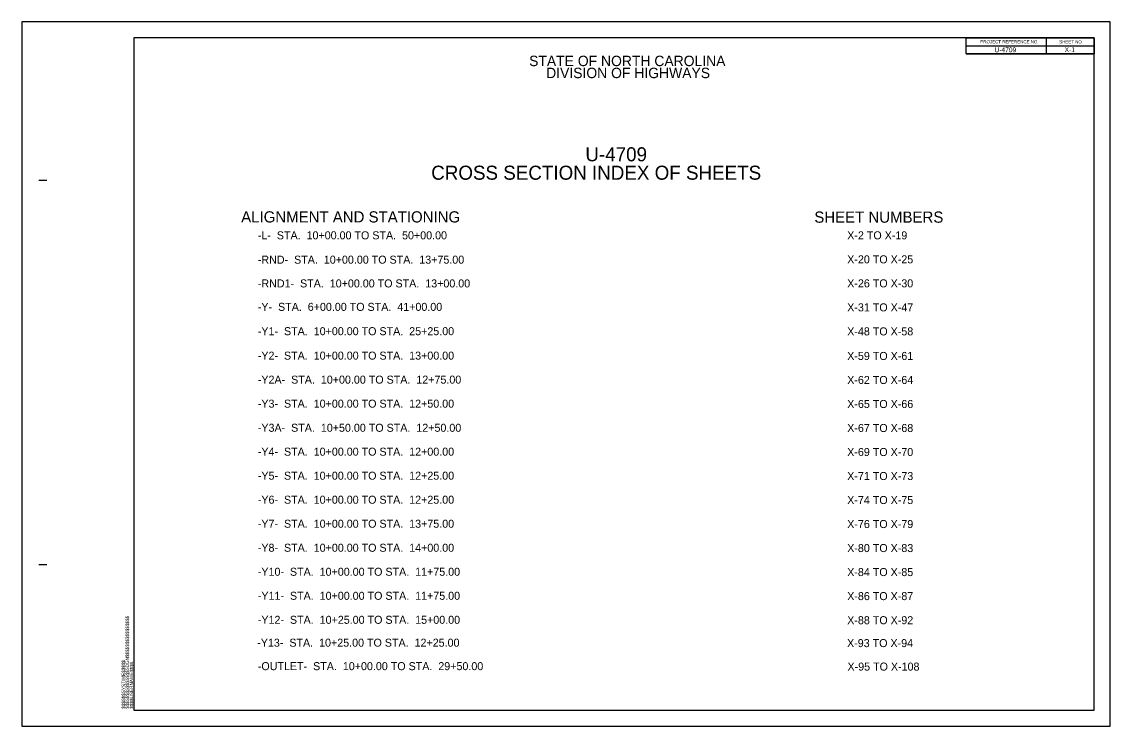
# Model space of a CAD drawing. Extents: x 573852.9 to 573886.9, y -53297.7 to -53275.7.
import ezdxf

# ---------------------------------------------------------------- set-up
doc = ezdxf.new("R2010")
doc.units = 0
for name, color, linetype in [('Sheet Data Field CELL', 7, 'Continuous'), ('Sheet Plot Border Outside CELL', 7, 'Continuous'), ('Sheet Summary CELL', 7, 'Continuous')]:
    doc.layers.add(name, color=color, linetype=linetype)

msp = doc.modelspace()

# ---------------------------------------------------------------- linework, layer by layer
at = {"layer": 'Sheet Plot Border Outside CELL'}
msp.add_lwpolyline([(573852.921, -53297.659), (573886.921, -53297.659), (573886.921, -53275.659), (573852.921, -53275.659)], close=True, dxfattribs=at)
at = {"layer": 'Sheet Summary CELL'}
for p, q in [((573856.421, -53276.159), (573856.421, -53276.968)), ((573884.921, -53276.16), (573884.921, -53276.66)), ((573882.42, -53276.41), (573886.421, -53276.41)), ((573882.42, -53276.66), (573886.421, -53276.66)), ((573853.451, -53280.609), (573853.701, -53280.609)), ((573853.451, -53292.609), (573853.701, -53292.609)), ((573856.421, -53297.159), (573856.421, -53297.159)), ((573856.421, -53297.159), (573856.421, -53297.159)), ((573856.421, -53297.159), (573856.421, -53297.159)), ((573856.421, -53297.159), (573856.421, -53297.159)), ((573856.421, -53297.159), (573856.421, -53297.159)), ((573856.421, -53297.159), (573856.421, -53297.159))]:
    msp.add_line(p, q, dxfattribs=at)
for points in [[(573886.421, -53276.159), (573856.421, -53276.159), (573856.421, -53297.159), (573886.421, -53297.159)], [(573882.42, -53276.159), (573886.421, -53276.159), (573886.421, -53276.66), (573882.42, -53276.66)]]:
    msp.add_lwpolyline(points, close=True, dxfattribs=at)
msp.add_lwpolyline([(573859.171, -53297.159), (573859.171, -53297.159)], dxfattribs=at)

# ---------------------------------------------------------------- texts
at = {"layer": 'Sheet Data Field CELL'}
for s, p in [('U-4709', (573883.305, -53276.61)), ('X-1', (573885.497, -53276.604))]:
    msp.add_text(s, height=0.15, dxfattribs=at).set_placement(p)
at = {"layer": 'Sheet Summary CELL'}
for s, height, p in [('PROJECT REFERENCE NO.', 0.1, (573882.864, -53276.333)), ('SHEET NO.', 0.1, (573885.327, -53276.335)), ('STATE OF NORTH CAROLINA', 0.325, (573868.769, -53277.044)), ('DIVISION OF HIGHWAYS', 0.325, (573869.301, -53277.419)), ('U-4709', 0.439, (573870.526, -53280.017)), ('CROSS SECTION INDEX OF SHEETS', 0.439, (573865.71, -53280.592)), ('ALIGNMENT AND STATIONING', 0.35, (573859.775, -53281.927)), ('SHEET NUMBERS', 0.35, (573877.677, -53281.934)), ('-L-  STA.  10+00.00 TO STA.  50+00.00', 0.25, (573860.294, -53282.453)), ('X-2 TO X-19', 0.25, (573878.705, -53282.453)), ('-RND-  STA.  10+00.00 TO STA.  13+75.00', 0.25, (573860.294, -53283.213)), ('X-20 TO X-25', 0.25, (573878.705, -53283.203)), ('-RND1-  STA.  10+00.00 TO STA.  13+00.00', 0.25, (573860.294, -53283.955)), ('X-26 TO X-30', 0.25, (573878.705, -53283.953)), ('-Y-  STA.  6+00.00 TO STA.  41+00.00', 0.25, (573860.294, -53284.687)), ('X-31 TO X-47', 0.25, (573878.705, -53284.703)), ('-Y1-  STA.  10+00.00 TO STA.  25+25.00', 0.25, (573860.294, -53285.447)), ('X-48 TO X-58', 0.25, (573878.705, -53285.453)), ('-Y2-  STA.  10+00.00 TO STA.  13+00.00', 0.25, (573860.294, -53286.21)), ('X-59 TO X-61', 0.25, (573878.705, -53286.22)), ('-Y2A-  STA.  10+00.00 TO STA.  12+75.00', 0.25, (573860.294, -53286.96)), ('X-62 TO X-64', 0.25, (573878.705, -53286.97)), ('-Y3-  STA.  10+00.00 TO STA.  12+50.00', 0.25, (573860.294, -53287.71)), ('X-65 TO X-66', 0.25, (573878.705, -53287.72)), ('-Y3A-  STA.  10+50.00 TO STA.  12+50.00', 0.25, (573860.294, -53288.463)), ('X-67 TO X-68', 0.25, (573878.705, -53288.47)), ('-Y4-  STA.  10+00.00 TO STA.  12+00.00', 0.25, (573860.294, -53289.21)), ('X-69 TO X-70', 0.25, (573878.705, -53289.22)), ('-Y5-  STA.  10+00.00 TO STA.  12+25.00', 0.25, (573860.294, -53289.96)), ('X-71 TO X-73', 0.25, (573878.705, -53289.97)), ('-Y6-  STA.  10+00.00 TO STA.  12+25.00', 0.25, (573860.294, -53290.71)), ('X-74 TO X-75', 0.25, (573878.705, -53290.72)), ('-Y7-  STA.  10+00.00 TO STA.  13+75.00', 0.25, (573860.294, -53291.46)), ('X-76 TO X-79', 0.25, (573878.705, -53291.47)), ('-Y8-  STA.  10+00.00 TO STA.  14+00.00', 0.25, (573860.294, -53292.21)), ('X-80 TO X-83', 0.25, (573878.705, -53292.22)), ('-Y10-  STA.  10+00.00 TO STA.  11+75.00', 0.25, (573860.294, -53292.96)), ('X-84 TO X-85', 0.25, (573878.705, -53292.97)), ('-Y11-  STA.  10+00.00 TO STA.  11+75.00', 0.25, (573860.294, -53293.71)), ('X-86 TO X-87', 0.25, (573878.705, -53293.72)), ('-Y12-  STA.  10+25.00 TO STA.  15+00.00', 0.25, (573860.294, -53294.46)), ('X-88 TO X-92', 0.25, (573878.705, -53294.473)), ('-Y13-  STA.  10+25.00 TO STA.  12+25.00', 0.25, (573860.276, -53295.175)), ('X-93 TO X-94', 0.25, (573878.7, -53295.188)), ('-OUTLET-  STA.  10+00.00 TO STA.  29+50.00', 0.25, (573860.294, -53295.908)), ('X-95 TO X-108', 0.25, (573878.714, -53295.921))]:
    msp.add_text(s, height=height, dxfattribs=at).set_placement(p)
for s, p in [('$$$$$$$$$$$$$$$$DGN$$$$$$$$$$$$$$$$', (573856.268, -53297.112)), ('$$$$$$SYSTIME$$$$$', (573856.147, -53297.112)), ('$$$$USERNAME$$$$', (573856.399, -53297.111))]:
    msp.add_text(s, height=0.105, rotation=90, dxfattribs=at).set_placement(p)

doc.saveas('drawing.dxf')
